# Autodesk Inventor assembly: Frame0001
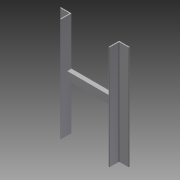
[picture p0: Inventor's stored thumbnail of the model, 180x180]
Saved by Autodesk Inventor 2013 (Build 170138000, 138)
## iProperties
Created: 2009-11
Part Number: Frame0001
Document SubType Name: Assembly
Designer: pokornp
Mass: 297817 g
Surface Area: 35410.7 cm^2
Volume: 37890.2 cm^3
Density: 7.86 g/cm^3
_FrameDoc: Frame Assembly
_Version: 15.0.0
Author: pokornp
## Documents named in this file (5)
- C:\Users\boganb\Documents\B2 Design\Goodyear\2013 Tutorial Files\Frame Analysis 1\Assembly2\Frame\Frame0001.iam
- C:\Users\boganb\Documents\B2 Design\Goodyear\2013 Tutorial Files\Frame Analysis 1\Assembly2\Frame\Skeleton0001.ipt
- C:\Users\boganb\Documents\B2 Design\Goodyear\2013 Tutorial Files\Frame Analysis 1\Assembly2\Frame\DIN L200x200x18 00000001.ipt
- C:\Users\boganb\Documents\B2 Design\Goodyear\2013 Tutorial Files\Frame Analysis 1\Assembly2\Frame\DIN L200x200x18 00000002.ipt
- C:\Users\boganb\Documents\B2 Design\Goodyear\2013 Tutorial Files\Frame Analysis 1\Assembly2\Frame\DIN 150 x 80 00000003.ipt
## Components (4 placed, 4 different names)
1. Frame Reference Model
2. DIN L200x200x18 00000001:1
3. DIN L200x200x18 00000002:1
4. DIN 150 x 80 00000003:1
